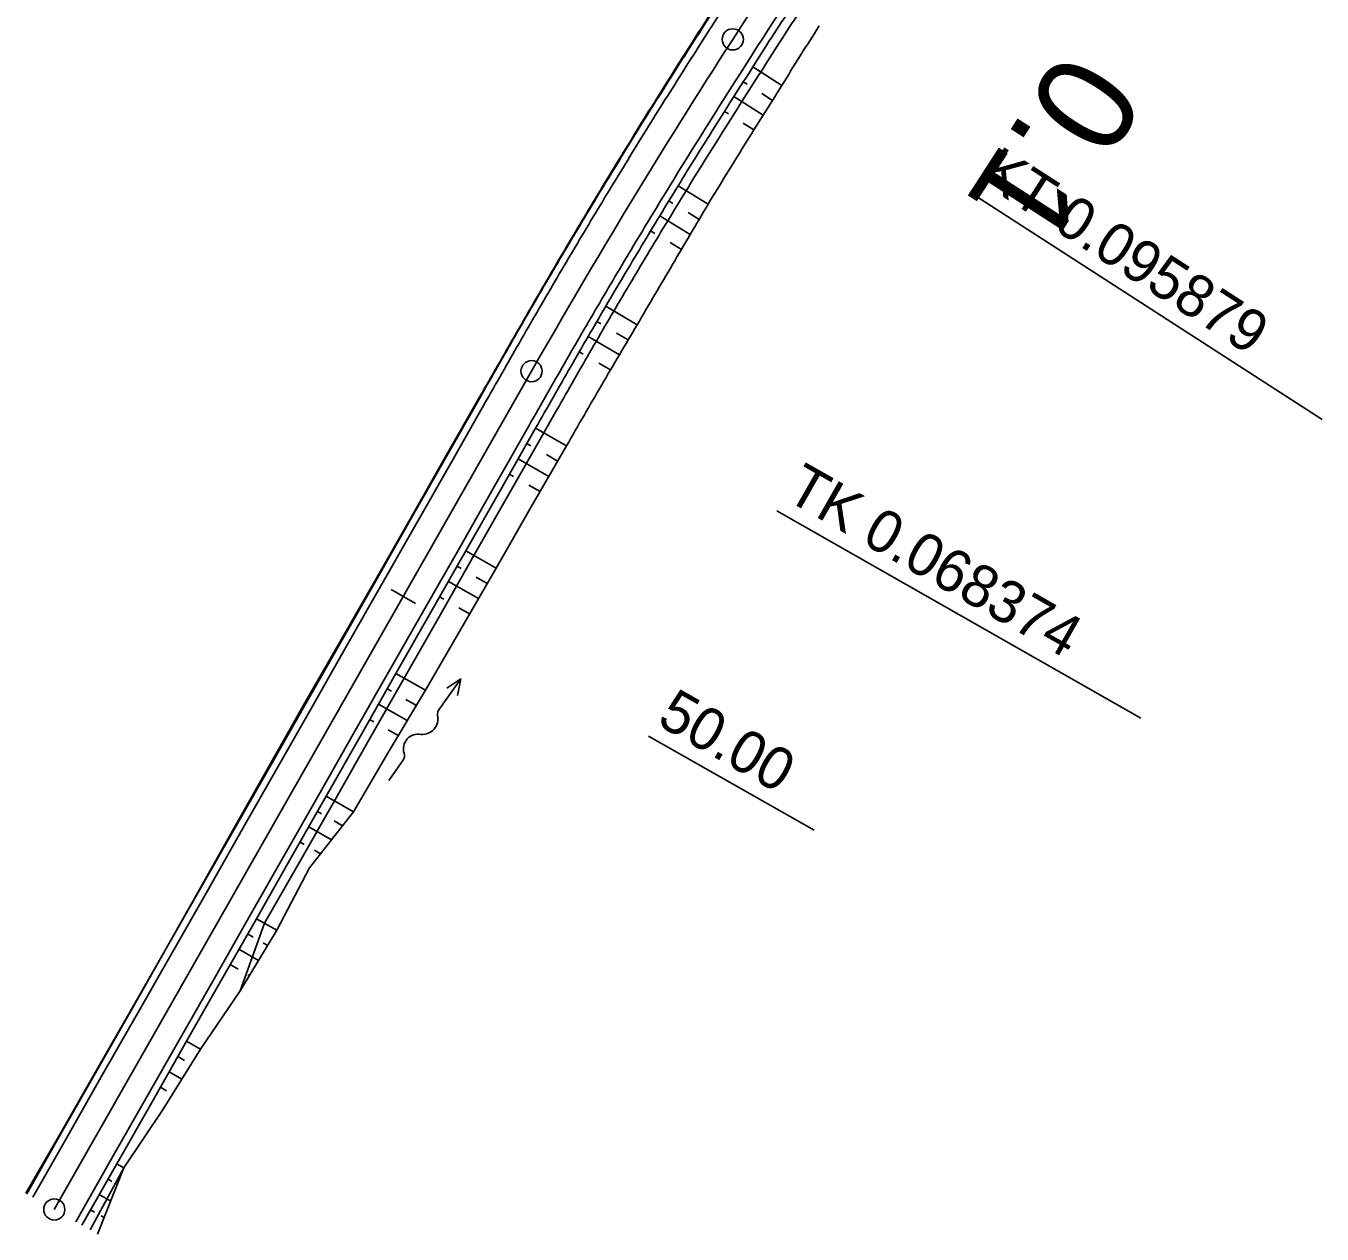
# Model space of a CAD drawing. Extents: x -481645 to -478728, y -1113199 to -1110710.
# Drawn here: x -479882.7 to -479790.8, y -1111791.4 to -1111705.7 of the extents above; entities that cross this region are included whole.
import ezdxf

# ---------------------------------------------------------------- set-up
doc = ezdxf.new("R2010")
doc.units = 0
for name, color, linetype in [('CP14_HATCH_SLOPE_L', 7, 'Continuous'), ('CP14_HECTOMETRY', 7, 'Continuous'), ('CP14_HLBODY', 7, 'Continuous'), ('CP1_HECTOMETRY', 7, 'Continuous'), ('O6_HATCH_SLOPE_L', 7, 'Continuous'), ('O6_HATCH_SLOPE_R', 7, 'Continuous'), ('O6_HECTOMETRY', 7, 'Continuous'), ('O6_HLBODY', 7, 'Continuous'), ('O6_HRANA_TELESO', 7, 'Continuous'), ('O6_OSA', 7, 'Continuous'), ('O6_VOZOVKA', 7, 'Continuous'), ('O6_ZPEVKRAJ', 7, 'Continuous')]:
    doc.layers.add(name, color=color, linetype=linetype)

# ---------------------------------------------------------------- blocks, each defined once
blk = doc.blocks.new('A$C70B')
at = {"layer": 'CP14_HLBODY'}
for p, q in [((0.869, 0.002), (-0.869, -0.002)), ((6.861, 0.426), (7.971, -0.002)), ((7.971, -0.002), (5.275, -0.002)), ((7.971, -0.002), (6.862, -0.478))]:
    blk.add_line(p, q, dxfattribs=at)
for centre, radius, start, end in [((0.872, 0.584), 0.582, 269.69241, 322.79009), ((2.168, -0.416), 1.055, 24.40393, 142.08362), ((4.08, 0.589), 1.109, 210.88731, 317.37071), ((5.319, -0.636), 0.636, 85.97658, 131.72478)]:
    blk.add_arc(centre, radius, start, end, dxfattribs=at)

msp = doc.modelspace()

# ---------------------------------------------------------------- linework, layer by layer
at = {"layer": 'CP14_HATCH_SLOPE_L'}
for p, q in [((-479831.189, -1111708.633), (-479829.134, -1111709.953)), ((-479831.86, -1111709.681), (-479831.579, -1111709.86)), ((-479832.528, -1111710.731), (-479830.456, -1111712.047)), ((-479830.547, -1111710.52), (-479829.796, -1111710.999)), ((-479833.194, -1111711.782), (-479832.912, -1111711.96)), ((-479831.872, -1111712.618), (-479831.113, -1111713.097)), ((-479836.484, -1111717.063), (-479834.36, -1111718.368)), ((-479837.134, -1111718.124), (-479836.85, -1111718.298)), ((-479837.781, -1111719.187), (-479835.622, -1111720.499)), ((-479835.778, -1111718.952), (-479834.992, -1111719.432)), ((-479838.426, -1111720.251), (-479838.141, -1111720.424)), ((-479837.052, -1111721.082), (-479836.248, -1111721.567)), ((-479841.61, -1111725.597), (-479839.38, -1111726.906)), ((-479842.238, -1111726.671), (-479841.95, -1111726.839)), ((-479842.864, -1111727.746), (-479840.644, -1111729.035)), ((-479840.838, -1111727.488), (-479840.014, -1111727.969)), ((-479843.488, -1111728.823), (-479843.199, -1111728.99)), ((-479842.091, -1111729.629), (-479841.272, -1111730.102)), ((-479846.581, -1111734.239), (-479844.394, -1111735.484)), ((-479847.2, -1111735.325), (-479846.91, -1111735.49)), ((-479847.818, -1111736.411), (-479845.642, -1111737.65)), ((-479845.819, -1111736.111), (-479845.018, -1111736.567)), ((-479848.437, -1111737.498), (-479848.147, -1111737.662)), ((-479847.062, -1111738.28), (-479846.266, -1111738.733)), ((-479851.529, -1111742.929), (-479849.386, -1111744.149)), ((-479852.148, -1111744.015), (-479851.858, -1111744.18)), ((-479852.766, -1111745.101), (-479850.634, -1111746.316)), ((-479850.79, -1111744.788), (-479850.01, -1111745.232)), ((-479853.385, -1111746.188), (-479853.096, -1111746.352)), ((-479852.032, -1111746.958), (-479851.258, -1111747.399)), ((-479856.478, -1111751.619), (-479854.387, -1111752.809)), ((-479857.096, -1111752.705), (-479856.806, -1111752.87)), ((-479855.774, -1111753.458), (-479855.03, -1111753.881)), ((-479857.715, -1111753.791), (-479855.674, -1111754.953)), ((-479858.333, -1111754.877), (-479858.044, -1111755.042)), ((-479857.036, -1111755.616), (-479856.317, -1111756.025)), ((-479861.426, -1111760.309), (-479859.478, -1111761.418)), ((-479862.044, -1111761.395), (-479861.754, -1111761.56)), ((-479862.663, -1111762.481), (-479861.039, -1111763.406)), ((-479860.862, -1111762.068), (-479860.259, -1111762.412)), ((-479863.281, -1111763.567), (-479862.992, -1111763.732)), ((-479862.261, -1111764.148), (-479861.82, -1111764.4)), ((-479866.374, -1111768.999), (-479864.927, -1111769.822)), ((-479866.993, -1111770.085), (-479866.609, -1111770.304)), ((-479865.9, -1111770.707), (-479865.575, -1111770.892)), ((-479867.611, -1111771.171), (-479866.222, -1111771.962)), ((-479868.23, -1111772.257), (-479867.658, -1111772.582)), ((-479866.978, -1111772.97), (-479866.87, -1111773.032)), ((-479871.322, -1111777.688), (-479870.342, -1111778.247)), ((-479871.941, -1111778.775), (-479871.472, -1111779.042)), ((-479872.559, -1111779.861), (-479871.663, -1111780.372)), ((-479871.002, -1111779.309), (-479871.002, -1111779.309)), ((-479873.178, -1111780.947), (-479872.75, -1111781.19)), ((-479872.323, -1111781.434), (-479872.323, -1111781.434)), ((-479876.271, -1111786.378), (-479875.758, -1111786.67)), ((-479876.889, -1111787.465), (-479876.625, -1111787.616)), ((-479876.294, -1111787.804), (-479876.228, -1111787.841)), ((-479877.508, -1111788.551), (-479876.697, -1111789.012)), ((-479878.126, -1111789.637), (-479877.845, -1111789.797)), ((-479877.366, -1111790.07), (-479877.167, -1111790.183))]:
    msp.add_line(p, q, dxfattribs=at)
at = {"layer": 'CP1_HECTOMETRY'}
for p, q in [((-479832.606, -1111706.678), (-479794.534, -1111647.625)), ((-479880.7, -1111789.61), (-479846.867, -1111730.194))]:
    msp.add_line(p, q, dxfattribs=at)
msp.add_arc((-479412.371, -1111977.607), 500, 147.18981, 150.34165, dxfattribs=at)
at = {"layer": 'O6_HATCH_SLOPE_L'}
msp.add_circle((-479880.7, -1111789.61), 0.75, dxfattribs=at)
at = {"layer": 'O6_HATCH_SLOPE_R'}
for p, q in [((-479834.975, -1111706.202), (-479835.024, -1111706.17)), ((-479835.68, -1111707.241), (-479835.7, -1111707.228)), ((-479835.652, -1111707.259), (-479835.657, -1111707.256)), ((-479836.327, -1111708.318), (-479836.374, -1111708.288)), ((-479837.026, -1111709.361), (-479837.045, -1111709.349)), ((-479836.999, -1111709.379), (-479837.003, -1111709.376)), ((-479840.318, -1111714.707), (-479840.359, -1111714.682)), ((-479840.998, -1111715.764), (-479841.014, -1111715.754)), ((-479840.974, -1111715.778), (-479840.978, -1111715.776)), ((-479841.627, -1111716.85), (-479841.666, -1111716.827)), ((-479842.3, -1111717.91), (-479842.315, -1111717.902)), ((-479842.278, -1111717.924), (-479842.282, -1111717.922)), ((-479845.49, -1111723.318), (-479845.519, -1111723.302)), ((-479846.143, -1111724.392), (-479846.153, -1111724.386)), ((-479846.125, -1111724.402), (-479846.129, -1111724.4)), ((-479846.756, -1111725.487), (-479846.784, -1111725.471)), ((-479847.403, -1111726.564), (-479847.412, -1111726.558)), ((-479847.385, -1111726.574), (-479847.389, -1111726.572)), ((-479850.491, -1111732.012), (-479850.527, -1111731.992)), ((-479851.133, -1111733.085), (-479851.147, -1111733.077)), ((-479851.11, -1111733.098), (-479851.114, -1111733.096)), ((-479851.729, -1111734.185), (-479851.768, -1111734.162)), ((-479852.372, -1111735.256), (-479852.389, -1111735.247)), ((-479852.347, -1111735.271), (-479852.352, -1111735.268)), ((-479855.44, -1111740.702), (-479855.481, -1111740.679)), ((-479856.084, -1111741.774), (-479856.101, -1111741.764)), ((-479856.058, -1111741.788), (-479856.062, -1111741.786)), ((-479856.677, -1111742.875), (-479856.722, -1111742.849)), ((-479857.323, -1111743.945), (-479857.342, -1111743.934)), ((-479857.295, -1111743.961), (-479857.299, -1111743.958)), ((-479860.388, -1111749.392), (-479860.444, -1111749.36)), ((-479861.04, -1111750.459), (-479861.065, -1111750.445)), ((-479861.007, -1111750.478), (-479861.011, -1111750.476)), ((-479861.625, -1111751.565), (-479861.686, -1111751.53)), ((-479862.279, -1111752.63), (-479862.307, -1111752.615)), ((-479862.244, -1111752.651), (-479862.248, -1111752.648)), ((-479865.336, -1111758.082), (-479865.403, -1111758.044)), ((-479865.991, -1111759.148), (-479866.018, -1111759.132)), ((-479865.955, -1111759.168), (-479865.96, -1111759.166)), ((-479866.573, -1111760.254), (-479866.633, -1111760.22)), ((-479867.225, -1111761.322), (-479867.249, -1111761.308)), ((-479867.192, -1111761.341), (-479867.196, -1111761.338)), ((-479870.285, -1111766.772), (-479870.312, -1111766.756)), ((-479870.92, -1111767.848), (-479870.928, -1111767.844)), ((-479870.903, -1111767.858), (-479870.908, -1111767.856)), ((-479871.522, -1111768.944), (-479871.544, -1111768.932)), ((-479872.154, -1111770.023), (-479872.16, -1111770.02)), ((-479872.14, -1111770.031), (-479872.144, -1111770.028)), ((-479875.233, -1111775.462), (-479875.249, -1111775.453)), ((-479875.865, -1111776.54), (-479875.87, -1111776.538)), ((-479875.851, -1111776.548), (-479875.856, -1111776.546)), ((-479876.47, -1111777.634), (-479876.491, -1111777.622)), ((-479877.104, -1111778.712), (-479877.111, -1111778.707)), ((-479877.088, -1111778.72), (-479877.092, -1111778.718)), ((-479880.181, -1111784.152), (-479880.211, -1111784.134)), ((-479880.822, -1111785.225), (-479880.836, -1111785.217)), ((-479880.8, -1111785.238), (-479880.804, -1111785.236)), ((-479881.418, -1111786.324), (-479881.46, -1111786.3)), ((-479882.065, -1111787.394), (-479882.085, -1111787.383)), ((-479882.037, -1111787.41), (-479882.041, -1111787.408))]:
    msp.add_line(p, q, dxfattribs=at)
at = {"layer": 'O6_HECTOMETRY'}
for p, q in [((-479815.797, -1111717.516), (-479790.835, -1111733.609)), ((-479829.487, -1111740.09), (-479803.678, -1111754.787))]:
    msp.add_line(p, q, dxfattribs=at)
for centre in [(-479832.606, -1111706.678), (-479846.867, -1111730.194), (-479880.7, -1111789.61)]:
    msp.add_circle(centre, 0.75, dxfattribs=at)
at = {"layer": 'O6_HLBODY'}
for p, q in [((-479855.09, -1111746.655), (-479856.828, -1111745.666)), ((-479838.579, -1111756.057), (-479826.847, -1111762.737))]:
    msp.add_line(p, q, dxfattribs=at)
at = {"layer": 'O6_HRANA_TELESO'}
for p, q in [((-479852.974, -1111736.352), (-479850.5, -1111732.007)), ((-479848.476, -1111738.914), (-479846.002, -1111734.569)), ((-479855.448, -1111740.697), (-479852.974, -1111736.352)), ((-479850.95, -1111743.259), (-479848.476, -1111738.914)), ((-479857.923, -1111745.042), (-479855.448, -1111740.697)), ((-479853.424, -1111747.604), (-479850.95, -1111743.259)), ((-479860.397, -1111749.387), (-479857.923, -1111745.042)), ((-479855.898, -1111751.949), (-479853.424, -1111747.604)), ((-479862.871, -1111753.732), (-479860.397, -1111749.387)), ((-479858.373, -1111756.293), (-479855.898, -1111751.949)), ((-479865.345, -1111758.077), (-479862.871, -1111753.732)), ((-479860.847, -1111760.638), (-479858.373, -1111756.293)), ((-479867.819, -1111762.422), (-479865.345, -1111758.077)), ((-479863.321, -1111764.983), (-479860.847, -1111760.638)), ((-479870.293, -1111766.767), (-479867.819, -1111762.422)), ((-479865.795, -1111769.328), (-479863.321, -1111764.983)), ((-479872.767, -1111771.112), (-479870.293, -1111766.767)), ((-479867.517, -1111774.102), (-479865.795, -1111769.328)), ((-479877.716, -1111779.802), (-479875.242, -1111775.457)), ((-479880.19, -1111784.147), (-479877.716, -1111779.802)), ((-479882.664, -1111788.492), (-479880.19, -1111784.147)), ((-479878.166, -1111791.053), (-479875.758, -1111786.67))]:
    msp.add_line(p, q, dxfattribs=at)
for centre, radius, start, end in [((-479622.55, -1111840.131), 251.13, 146.62782, 147.7695), ((-479620.373, -1111841.53), 248.542, 146.62285, 147.77432), ((-479412.371, -1111977.607), 502.26, 147.29051, 147.86347), ((-479412.371, -1111977.607), 497.084, 147.29051, 147.86346), ((-479412.371, -1111977.607), 502.26, 147.86346, 148.43642), ((-479412.371, -1111977.607), 497.084, 147.86346, 148.43642), ((-479412.371, -1111977.607), 502.26, 148.43642, 149.00938), ((-479412.371, -1111977.607), 497.084, 148.43642, 149.00938), ((-479412.371, -1111977.607), 502.26, 149.00938, 149.58234), ((-479412.371, -1111977.607), 497.084, 149.00938, 149.58234), ((-479412.371, -1111977.607), 502.26, 149.58234, 150.15529), ((-479412.371, -1111977.607), 497.084, 149.58233, 150.15529), ((-478540.279, -1112476.121), 1506.78, 150.216047, 150.406453), ((-478549.273, -1112470.994), 1491.251, 150.215592, 150.407333)]:
    msp.add_arc(centre, radius, start, end, dxfattribs=at)
at = {"layer": 'O6_OSA'}
for p, q in [((-479853.01, -1111736.332), (-479850.527, -1111731.992)), ((-479846.891, -1111739.816), (-479844.394, -1111735.484)), ((-479855.481, -1111740.679), (-479853.01, -1111736.332)), ((-479849.386, -1111744.149), (-479846.891, -1111739.816)), ((-479857.962, -1111745.02), (-479855.481, -1111740.679)), ((-479851.881, -1111748.482), (-479849.386, -1111744.149)), ((-479860.444, -1111749.36), (-479857.962, -1111745.02)), ((-479854.387, -1111752.809), (-479851.881, -1111748.482)), ((-479862.928, -1111753.699), (-479860.444, -1111749.36)), ((-479856.961, -1111757.097), (-479854.387, -1111752.809)), ((-479865.403, -1111758.044), (-479862.928, -1111753.699)), ((-479859.478, -1111761.418), (-479856.961, -1111757.097)), ((-479867.864, -1111762.397), (-479865.403, -1111758.044)), ((-479862.6, -1111765.394), (-479859.478, -1111761.418)), ((-479870.312, -1111766.756), (-479867.864, -1111762.397)), ((-479864.927, -1111769.822), (-479862.6, -1111765.394)), ((-479872.775, -1111771.107), (-479870.312, -1111766.756)), ((-479867.517, -1111774.102), (-479864.927, -1111769.822)), ((-479875.249, -1111775.453), (-479872.775, -1111771.107)), ((-479870.342, -1111778.247), (-479867.517, -1111774.102)), ((-479877.732, -1111779.792), (-479875.249, -1111775.453)), ((-479872.983, -1111782.497), (-479870.342, -1111778.247)), ((-479880.211, -1111784.134), (-479877.732, -1111779.792)), ((-479875.758, -1111786.67), (-479872.983, -1111782.497)), ((-479882.709, -1111788.466), (-479880.211, -1111784.134)), ((-479877.637, -1111791.354), (-479875.758, -1111786.67))]:
    msp.add_line(p, q, dxfattribs=at)
for centre, radius, start, end in [((-479622.428, -1111839.891), 251.154, 146.68899, 147.83058), ((-479412.126, -1111977.22), 502.306, 147.34277, 147.91573), ((-479617.986, -1111839.371), 247.654, 147.33984, 148.49482), ((-479410.942, -1111975.344), 495.295, 147.6002, 148.17316), ((-479412.093, -1111977.16), 502.301, 147.92357, 148.49653), ((-479412.023, -1111977.033), 502.295, 148.51303, 149.08599), ((-479411.13, -1111975.599), 495.269, 148.13661, 148.70957), ((-479408.813, -1111971.657), 495.223, 149.23845, 149.81147), ((-479411.919, -1111976.845), 502.287, 149.11049, 149.68345), ((-479411.172, -1111975.578), 495.177, 149.28212, 149.85509), ((-479412.281, -1111977.451), 502.282, 149.60291, 150.17587), ((-478541.664, -1112478.622), 1506.843, 150.107369, 150.297769), ((-479414.215, -1111980.757), 495.183, 149.16007, 149.73304), ((-478557.289, -1112477.361), 1485.604, 149.848969, 150.041208)]:
    msp.add_arc(centre, radius, start, end, dxfattribs=at)
at = {"layer": 'O6_VOZOVKA'}
for p, q in [((-479852.531, -1111736.605), (-479850.057, -1111732.26)), ((-479849.49, -1111738.336), (-479847.016, -1111733.992)), ((-479855.005, -1111740.95), (-479852.531, -1111736.605)), ((-479851.964, -1111742.681), (-479849.49, -1111738.336)), ((-479857.479, -1111745.294), (-479855.005, -1111740.95)), ((-479854.438, -1111747.026), (-479851.964, -1111742.681)), ((-479859.954, -1111749.639), (-479857.479, -1111745.294)), ((-479856.912, -1111751.371), (-479854.438, -1111747.026)), ((-479862.428, -1111753.984), (-479859.954, -1111749.639)), ((-479859.386, -1111755.716), (-479856.912, -1111751.371)), ((-479864.902, -1111758.329), (-479862.428, -1111753.984)), ((-479861.86, -1111760.061), (-479859.386, -1111755.716)), ((-479867.376, -1111762.674), (-479864.902, -1111758.329)), ((-479864.334, -1111764.406), (-479861.86, -1111760.061)), ((-479869.85, -1111767.019), (-479867.376, -1111762.674)), ((-479866.809, -1111768.751), (-479864.334, -1111764.406)), ((-479872.324, -1111771.364), (-479869.85, -1111767.019)), ((-479869.283, -1111773.096), (-479866.809, -1111768.751)), ((-479874.798, -1111775.709), (-479872.324, -1111771.364)), ((-479871.757, -1111777.441), (-479869.283, -1111773.096)), ((-479877.272, -1111780.054), (-479874.798, -1111775.709)), ((-479874.231, -1111781.786), (-479871.757, -1111777.441)), ((-479879.747, -1111784.399), (-479877.272, -1111780.054)), ((-479876.705, -1111786.131), (-479874.231, -1111781.786)), ((-479882.221, -1111788.744), (-479879.747, -1111784.399)), ((-479879.179, -1111790.476), (-479876.705, -1111786.131))]:
    msp.add_line(p, q, dxfattribs=at)
for centre, radius, start, end in [((-479622.336, -1111840.268), 250.875, 146.62733, 147.76997), ((-479620.863, -1111841.214), 249.125, 146.62398, 147.77323), ((-479412.371, -1111977.607), 501.75, 147.29051, 147.86347), ((-479412.371, -1111977.607), 498.25, 147.29051, 147.86346), ((-479412.371, -1111977.607), 501.75, 147.86346, 148.43642), ((-479412.371, -1111977.607), 498.25, 147.86346, 148.43642), ((-479412.371, -1111977.607), 501.75, 148.43642, 149.00938), ((-479412.371, -1111977.607), 498.25, 148.43642, 149.00938), ((-479412.371, -1111977.607), 501.75, 149.00938, 149.58234), ((-479412.371, -1111977.607), 498.25, 149.00938, 149.58234), ((-479412.371, -1111977.607), 501.75, 149.58234, 150.15529), ((-479412.371, -1111977.607), 498.25, 149.58233, 150.15529), ((-478541.165, -1112475.616), 1505.25, 150.216003, 150.406539), ((-478547.246, -1112472.149), 1494.75, 150.215694, 150.407133)]:
    msp.add_arc(centre, radius, start, end, dxfattribs=at)
at = {"layer": 'O6_ZPEVKRAJ'}
for p, q in [((-479852.966, -1111736.357), (-479850.491, -1111732.012)), ((-479849.055, -1111738.584), (-479846.581, -1111734.239)), ((-479855.44, -1111740.702), (-479852.966, -1111736.357)), ((-479851.529, -1111742.929), (-479849.055, -1111738.584)), ((-479857.914, -1111745.047), (-479855.44, -1111740.702)), ((-479854.003, -1111747.274), (-479851.529, -1111742.929)), ((-479860.388, -1111749.392), (-479857.914, -1111745.047)), ((-479856.478, -1111751.619), (-479854.003, -1111747.274)), ((-479862.862, -1111753.737), (-479860.388, -1111749.392)), ((-479858.952, -1111755.964), (-479856.478, -1111751.619)), ((-479865.336, -1111758.082), (-479862.862, -1111753.737)), ((-479861.426, -1111760.309), (-479858.952, -1111755.964)), ((-479867.81, -1111762.427), (-479865.336, -1111758.082)), ((-479863.9, -1111764.654), (-479861.426, -1111760.309)), ((-479870.285, -1111766.772), (-479867.81, -1111762.427)), ((-479866.374, -1111768.999), (-479863.9, -1111764.654)), ((-479872.759, -1111771.117), (-479870.285, -1111766.772)), ((-479868.848, -1111773.344), (-479866.374, -1111768.999)), ((-479875.233, -1111775.462), (-479872.759, -1111771.117)), ((-479871.322, -1111777.688), (-479868.848, -1111773.344)), ((-479877.707, -1111779.807), (-479875.233, -1111775.462)), ((-479873.796, -1111782.033), (-479871.322, -1111777.688)), ((-479880.181, -1111784.152), (-479877.707, -1111779.807)), ((-479876.271, -1111786.378), (-479873.796, -1111782.033)), ((-479882.655, -1111788.497), (-479880.181, -1111784.152)), ((-479878.745, -1111790.723), (-479876.271, -1111786.378))]:
    msp.add_line(p, q, dxfattribs=at)
for centre, radius, start, end in [((-479622.546, -1111840.133), 251.125, 146.62781, 147.76951), ((-479620.653, -1111841.35), 248.875, 146.62349, 147.7737), ((-479412.371, -1111977.607), 502.25, 147.29051, 147.86347), ((-479412.371, -1111977.607), 497.75, 147.29051, 147.86346), ((-479412.371, -1111977.607), 502.25, 147.86346, 148.43642), ((-479412.371, -1111977.607), 497.75, 147.86346, 148.43642), ((-479412.371, -1111977.607), 502.25, 148.43642, 149.00938), ((-479412.371, -1111977.607), 497.75, 148.43642, 149.00938), ((-479412.371, -1111977.607), 502.25, 149.00938, 149.58234), ((-479412.371, -1111977.607), 497.75, 149.00938, 149.58234), ((-479412.371, -1111977.607), 502.25, 149.58234, 150.15529), ((-479412.371, -1111977.607), 497.75, 149.58233, 150.15529), ((-478540.296, -1112476.112), 1506.75, 150.216047, 150.406456), ((-478548.115, -1112471.654), 1493.25, 150.21565, 150.407219)]:
    msp.add_arc(centre, radius, start, end, dxfattribs=at)

# ---------------------------------------------------------------- block references
at = {"layer": 'CP14_HECTOMETRY', "rotation": 54.65738326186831}
msp.add_blockref('A$C70B', (-479856.489, -1111758.499), dxfattribs=at)

# ---------------------------------------------------------------- texts
at = {"layer": 'O6_HATCH_SLOPE_L'}
msp.add_text('0.1', height=6.999, rotation=237.14418, dxfattribs=at).set_placement((-479809.133, -1111707.192))
at = {"layer": 'O6_HECTOMETRY'}
for s, height, rotation, p in [('KT 0.095879', 3, 327.1898, (-479815.256, -1111716.675)), ('TK 0.068374', 2.999, 330.34165, (-479828.993, -1111739.221))]:
    msp.add_text(s, height=height, rotation=rotation, dxfattribs=at).set_placement(p)
at = {"layer": 'O6_HLBODY'}
msp.add_text('50.00', height=2.999, rotation=330.34165, dxfattribs=at).set_placement((-479838.085, -1111755.188))

doc.saveas('drawing.dxf')
